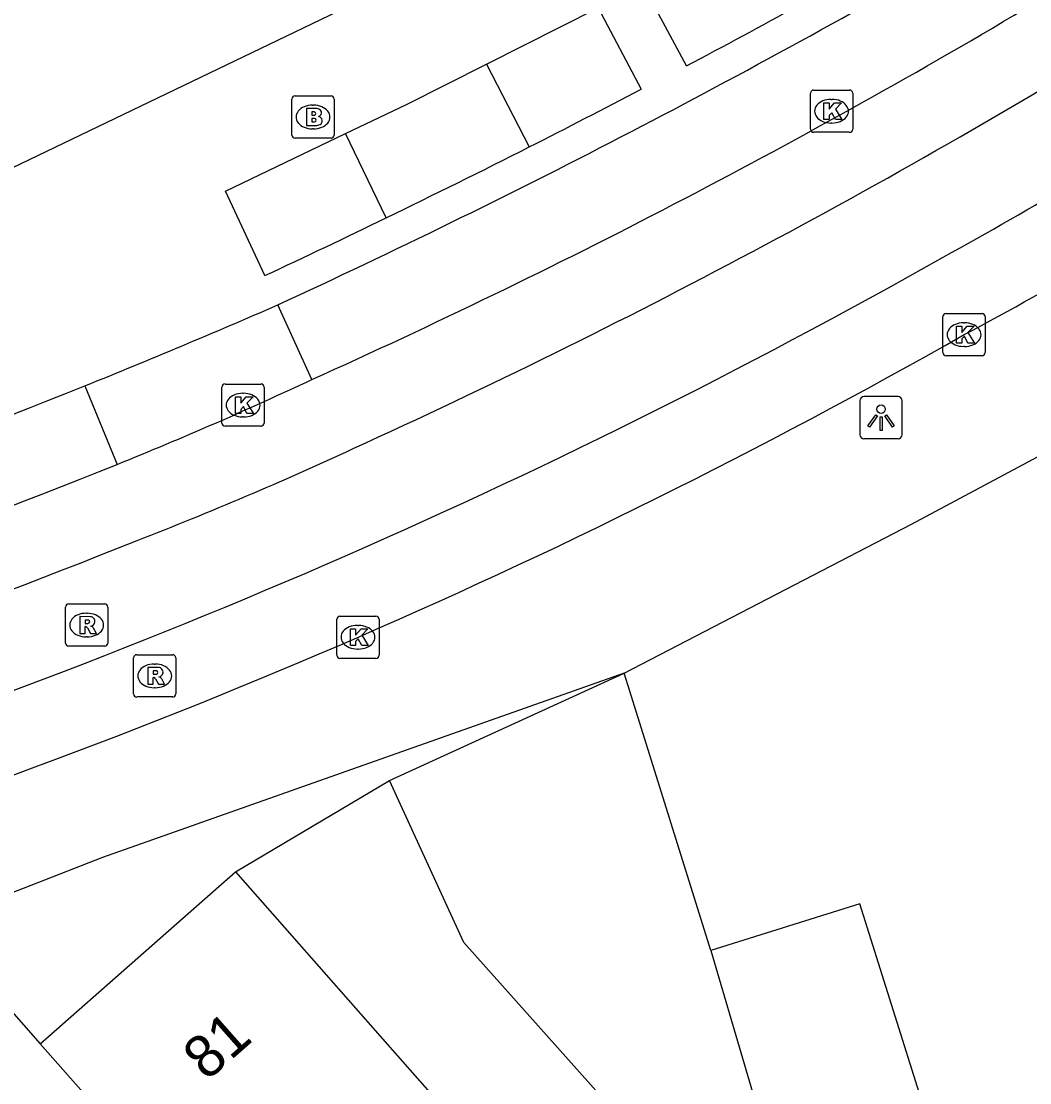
# Model space of a CAD drawing. Extents: x 161355 to 162026, y 386504 to 387459.
# Drawn here: x 161546.63 to 161570.51, y 386818.81 to 386843.94 of the extents above; entities that cross this region are included whole.
import ezdxf

# ---------------------------------------------------------------- set-up
doc = ezdxf.new("R2010")
doc.units = 0
for name, color, linetype in [('IMGEO_Brandkraan', 7, 'Continuous'), ('IMGEO_Groenvoorziening', 7, 'Continuous'), ('IMGEO_Kolk', 7, 'Continuous'), ('IMGEO_Lichtpunt', 7, 'Continuous'), ('IMGEO_Pand', 7, 'Continuous'), ('IMGEO_Pand_nummerreeks', 7, 'Continuous'), ('IMGEO_Rijbaan_lokaal_gesloten', 7, 'Continuous'), ('IMGEO_Rijbaan_lokaal_open', 7, 'Continuous'), ('IMGEO_Rioolput', 7, 'Continuous'), ('IMGEO_Voetpad_open', 7, 'Continuous')]:
    doc.layers.add(name, color=color, linetype=linetype)

msp = doc.modelspace()

# ---------------------------------------------------------------- linework, layer by layer
at = {"layer": 'IMGEO_Brandkraan'}
for p, q in [((161553.116, 386842.176), (161553.968, 386842.176)), ((161553.041, 386841.25), (161553.041, 386842.102)), ((161553.529, 386841.956), (161553.554, 386841.956)), ((161554.042, 386842.102), (161554.042, 386841.25)), ((161553.552, 386841.396), (161553.527, 386841.396)), ((161553.968, 386841.176), (161553.116, 386841.176))]:
    msp.add_line(p, q, dxfattribs=at)
for points in [[(161553.116, 386842.176), (161553.968, 386842.176)], [(161553.041, 386841.25), (161553.041, 386842.102)], [(161554.042, 386842.102), (161554.042, 386841.25)], [(161553.389, 386841.876), (161553.389, 386841.476), (161553.602, 386841.476)], [(161553.62, 386841.876), (161553.389, 386841.876)], [(161553.568, 386841.795), (161553.514, 386841.795), (161553.514, 386841.719)], [(161553.514, 386841.719), (161553.567, 386841.719)], [(161553.576, 386841.643), (161553.514, 386841.643), (161553.514, 386841.562)], [(161553.514, 386841.562), (161553.576, 386841.562)], [(161553.968, 386841.176), (161553.116, 386841.176)]]:
    msp.add_lwpolyline(points, dxfattribs=at)
for centre, radius, start, end in [((161553.118, 386842.1), 0.0765, 91.552, 178.448), ((161553.118, 386842.1), 0.0765, 91.552, 178.448), ((161553.966, 386842.1), 0.0765, 1.552, 88.448), ((161553.966, 386842.1), 0.0765, 1.552, 88.448), ((161553.569, 386841.757), 0.0379, 267.8285, 90.9355), ((161553.577, 386841.602), 0.0404, 269.8759, 90.5077), ((161553.624, 386841.731), 0.145, 59.4692, 91.5367), ((161553.649, 386841.778), 0.0922, 285.5137, 58.1501), ((161553.654, 386841.586), 0.105, 301.3115, 78.989), ((161553.608, 386841.727), 0.251, 268.6676, 293.5347), ((161553.118, 386841.252), 0.0765, 181.552, 268.448), ((161553.118, 386841.252), 0.0765, 181.552, 268.448), ((161553.966, 386841.252), 0.0765, 271.552, 358.448), ((161553.966, 386841.252), 0.0765, 271.552, 358.448)]:
    msp.add_arc(centre, radius, start, end, dxfattribs=at)
for centre, major_axis, ratio, start_param, end_param in [((161553.528, 386841.676), (-0.387, 0.002), 0.722429, 4.712389, 7.853982), ((161553.553, 386841.676), (-0.39, 0.002), 0.717154, 1.570796, 4.712389)]:
    msp.add_ellipse(centre, major_axis=major_axis, ratio=ratio, start_param=start_param, end_param=end_param, dxfattribs=at)
at = {"layer": 'IMGEO_Groenvoorziening'}
for points in [[(161557.648, 386842.93), (161558.662, 386840.969)], [(161555.27, 386839.287), (161554.307, 386841.282)]]:
    msp.add_lwpolyline(points, dxfattribs=at)
at = {"layer": 'IMGEO_Kolk'}
for p, q in [((161565.317, 386841.388), (161565.317, 386842.24)), ((161565.392, 386842.314), (161566.244, 386842.314)), ((161566.318, 386842.24), (161566.318, 386841.388)), ((161565.805, 386842.094), (161565.83, 386842.094)), ((161565.828, 386841.534), (161565.803, 386841.534)), ((161566.244, 386841.314), (161565.392, 386841.314)), ((161568.455, 386836.098), (161568.455, 386836.95)), ((161568.53, 386837.024), (161569.382, 386837.024)), ((161569.456, 386836.95), (161569.456, 386836.098)), ((161568.943, 386836.804), (161568.968, 386836.804)), ((161568.966, 386836.244), (161568.941, 386836.244)), ((161569.382, 386836.024), (161568.53, 386836.024)), ((161551.385, 386834.429), (161551.385, 386835.281)), ((161551.46, 386835.355), (161552.312, 386835.355)), ((161551.873, 386835.135), (161551.898, 386835.135)), ((161552.386, 386835.281), (161552.386, 386834.429)), ((161552.312, 386834.355), (161551.46, 386834.355)), ((161551.896, 386834.575), (161551.871, 386834.575)), ((161554.18, 386829.86), (161555.032, 386829.86)), ((161554.105, 386828.934), (161554.105, 386829.786)), ((161554.593, 386829.64), (161554.618, 386829.64)), ((161555.106, 386829.786), (161555.106, 386828.934)), ((161554.616, 386829.08), (161554.591, 386829.08)), ((161555.032, 386828.86), (161554.18, 386828.86))]:
    msp.add_line(p, q, dxfattribs=at)
for points in [[(161565.317, 386841.388), (161565.317, 386842.24)], [(161565.392, 386842.314), (161566.244, 386842.314)], [(161566.318, 386842.24), (161566.318, 386841.388)], [(161565.638, 386842.014), (161565.761, 386842.014), (161565.761, 386841.863), (161565.891, 386842.014), (161566.055, 386842.014), (161565.909, 386841.863), (161566.062, 386841.614), (161565.91, 386841.614), (161565.825, 386841.778), (161565.761, 386841.711), (161565.761, 386841.614), (161565.638, 386841.614), (161565.638, 386842.014)], [(161566.244, 386841.314), (161565.392, 386841.314)], [(161568.455, 386836.098), (161568.455, 386836.95)], [(161568.53, 386837.024), (161569.382, 386837.024)], [(161569.456, 386836.95), (161569.456, 386836.098)], [(161568.776, 386836.724), (161568.899, 386836.724), (161568.899, 386836.573), (161569.029, 386836.724), (161569.193, 386836.724), (161569.047, 386836.573), (161569.2, 386836.324), (161569.048, 386836.324), (161568.963, 386836.488), (161568.899, 386836.421), (161568.899, 386836.324), (161568.776, 386836.324), (161568.776, 386836.724)], [(161569.382, 386836.024), (161568.53, 386836.024)], [(161551.385, 386834.429), (161551.385, 386835.281)], [(161551.46, 386835.355), (161552.312, 386835.355)], [(161552.386, 386835.281), (161552.386, 386834.429)], [(161551.706, 386835.055), (161551.829, 386835.055), (161551.829, 386834.904), (161551.959, 386835.055), (161552.123, 386835.055), (161551.977, 386834.904), (161552.13, 386834.655), (161551.978, 386834.655), (161551.893, 386834.819), (161551.829, 386834.752), (161551.829, 386834.655), (161551.706, 386834.655), (161551.706, 386835.055)], [(161552.312, 386834.355), (161551.46, 386834.355)], [(161554.18, 386829.86), (161555.032, 386829.86)], [(161554.105, 386828.934), (161554.105, 386829.786)], [(161555.106, 386829.786), (161555.106, 386828.934)], [(161554.426, 386829.56), (161554.549, 386829.56), (161554.549, 386829.409), (161554.679, 386829.56), (161554.843, 386829.56), (161554.697, 386829.409), (161554.85, 386829.16), (161554.698, 386829.16), (161554.613, 386829.324), (161554.549, 386829.257), (161554.549, 386829.16), (161554.426, 386829.16), (161554.426, 386829.56)], [(161555.032, 386828.86), (161554.18, 386828.86)]]:
    msp.add_lwpolyline(points, dxfattribs=at)
for centre, start, end in [((161565.394, 386842.238), 91.552, 178.448), ((161565.394, 386842.238), 91.552, 178.448), ((161566.242, 386842.238), 1.552, 88.448), ((161566.242, 386842.238), 1.552, 88.448), ((161565.394, 386841.39), 181.552, 268.448), ((161565.394, 386841.39), 181.552, 268.448), ((161566.242, 386841.39), 271.552, 358.448), ((161566.242, 386841.39), 271.552, 358.448), ((161568.532, 386836.948), 91.552, 178.448), ((161568.532, 386836.948), 91.552, 178.448), ((161569.38, 386836.948), 1.552, 88.448), ((161569.38, 386836.948), 1.552, 88.448), ((161568.532, 386836.1), 181.552, 268.448), ((161568.532, 386836.1), 181.552, 268.448), ((161569.38, 386836.1), 271.552, 358.448), ((161569.38, 386836.1), 271.552, 358.448), ((161551.462, 386835.279), 91.552, 178.448), ((161551.462, 386835.279), 91.552, 178.448), ((161552.31, 386835.279), 1.552, 88.448), ((161552.31, 386835.279), 1.552, 88.448), ((161551.462, 386834.431), 181.552, 268.448), ((161551.462, 386834.431), 181.552, 268.448), ((161552.31, 386834.431), 271.552, 358.448), ((161552.31, 386834.431), 271.552, 358.448), ((161554.182, 386829.784), 91.552, 178.448), ((161554.182, 386829.784), 91.552, 178.448), ((161555.03, 386829.784), 1.552, 88.448), ((161555.03, 386829.784), 1.552, 88.448), ((161554.182, 386828.936), 181.552, 268.448), ((161554.182, 386828.936), 181.552, 268.448), ((161555.03, 386828.936), 271.552, 358.448), ((161555.03, 386828.936), 271.552, 358.448)]:
    msp.add_arc(centre, 0.0765, start, end, dxfattribs=at)
for centre, major_axis, ratio, start_param, end_param in [((161565.804, 386841.814), (-0.387, 0.002), 0.722429, 4.712389, 7.853982), ((161565.829, 386841.814), (-0.39, 0.002), 0.717154, 1.570796, 4.712389), ((161568.942, 386836.524), (-0.387, 0.002), 0.722429, 4.712389, 7.853982), ((161568.967, 386836.524), (-0.39, 0.002), 0.717154, 1.570796, 4.712389), ((161551.872, 386834.855), (-0.387, 0.002), 0.722429, 4.712389, 7.853982), ((161551.897, 386834.855), (-0.39, 0.002), 0.717154, 1.570796, 4.712389), ((161554.592, 386829.36), (-0.387, 0.002), 0.722429, 4.712389, 7.853982), ((161554.617, 386829.36), (-0.39, 0.002), 0.717154, 1.570796, 4.712389)]:
    msp.add_ellipse(centre, major_axis=major_axis, ratio=ratio, start_param=start_param, end_param=end_param, dxfattribs=at)
at = {"layer": 'IMGEO_Lichtpunt'}
for p, q in [((161566.491, 386834.962), (161566.491, 386834.155)), ((161566.491, 386834.962), (161566.491, 386834.155)), ((161567.393, 386835.057), (161566.585, 386835.057)), ((161567.393, 386835.057), (161566.585, 386835.057)), ((161567.487, 386834.155), (161567.487, 386834.962)), ((161567.487, 386834.155), (161567.487, 386834.962)), ((161566.585, 386834.061), (161567.393, 386834.061)), ((161566.585, 386834.061), (161567.393, 386834.061))]:
    msp.add_line(p, q, dxfattribs=at)
for points in [[(161566.865, 386834.626), (161566.904, 386834.598), (161566.716, 386834.336), (161566.678, 386834.363), (161566.865, 386834.626)], [(161567.077, 386834.598), (161567.115, 386834.625), (161567.302, 386834.363), (161567.263, 386834.335), (161567.077, 386834.598)], [(161566.967, 386834.578), (161567.014, 386834.578), (161567.014, 386834.256), (161566.967, 386834.256), (161566.967, 386834.578)]]:
    msp.add_lwpolyline(points, dxfattribs=at)
msp.add_circle((161566.99, 386834.76), 0.0994, dxfattribs=at)
for centre, start, end in [((161566.585, 386834.962), 90, 180), ((161566.585, 386834.962), 90, 180), ((161567.393, 386834.962), 0, 90), ((161567.393, 386834.962), 0, 90), ((161566.585, 386834.155), 180, 270), ((161566.585, 386834.155), 180, 270), ((161567.393, 386834.155), 270, 0), ((161567.393, 386834.155), 270, 360)]:
    msp.add_arc(centre, 0.0946, start, end, dxfattribs=at)
at = {"layer": 'IMGEO_Pand'}
for points in [[(161555.353, 386825.969), (161560.908, 386828.506)], [(161562.963, 386821.942), (161561.042, 386828.079), (161560.908, 386828.506)], [(161564.024, 386818.32), (161562.065, 386816.575), (161557.114, 386822.131), (161555.353, 386825.969)], [(161547.085, 386819.73), (161551.704, 386823.803)], [(161551.704, 386823.803), (161555.01, 386820.052), (161557.658, 386817.049), (161559.775, 386814.648), (161555.164, 386810.583)], [(161568.624, 386812.203), (161567.681, 386815.202), (161568.843, 386815.568), (161567.989, 386818.282), (161566.488, 386823.051), (161562.963, 386821.942)], [(161562.963, 386821.942), (161564.024, 386818.32)], [(161540.906, 386817.019), (161545.726, 386821.269), (161547.085, 386819.73)], [(161555.164, 386810.583), (161547.085, 386819.73)]]:
    msp.add_lwpolyline(points, dxfattribs=at)
at = {"layer": 'IMGEO_Rijbaan_lokaal_gesloten'}
for centre, radius, start, end in [((161484.617, 386988.619), 167.941, 294.21901, 300.71532), ((161483.765, 386989.11), 170.634, 294.48882, 301.57465), ((161507.605, 386948.155), 125.538, 298.78933, 302.11626), ((161526.3, 386916.738), 90.851, 298.00279, 302.67491), ((161491.859, 386973.935), 155.72, 287.22198, 299.29875), ((161494.805, 386967.101), 150.162, 286.97418, 299.59125), ((161514.694, 386918.245), 91.434, 291.97075, 295.12092), ((161518.235, 386912.068), 86.236, 291.1677, 294.86432), ((161488.255, 386984.249), 162.536, 281.2692, 291.90897), ((161488.231, 386983.377), 163.583, 281.3297, 291.94879)]:
    msp.add_arc(centre, radius, start, end, dxfattribs=at)
at = {"layer": 'IMGEO_Rijbaan_lokaal_open'}
for points in [[(161553.511, 386835.459), (161552.706, 386837.228)], [(161548.14, 386835.312), (161548.903, 386833.451)]]:
    msp.add_lwpolyline(points, dxfattribs=at)
msp.add_arc((161480.876, 387002.007), 179.755, 291.97487, 293.55325, dxfattribs=at)
at = {"layer": 'IMGEO_Rioolput'}
for p, q in [((161547.758, 386830.148), (161548.61, 386830.148)), ((161547.683, 386829.222), (161547.683, 386830.074)), ((161548.171, 386829.928), (161548.196, 386829.928)), ((161548.684, 386830.074), (161548.684, 386829.222)), ((161548.194, 386829.368), (161548.169, 386829.368)), ((161548.61, 386829.148), (161547.758, 386829.148)), ((161549.294, 386828.019), (161549.294, 386828.871)), ((161549.369, 386828.945), (161550.221, 386828.945)), ((161550.295, 386828.871), (161550.295, 386828.019)), ((161549.782, 386828.725), (161549.807, 386828.725)), ((161549.805, 386828.165), (161549.78, 386828.165)), ((161550.221, 386827.945), (161549.369, 386827.945))]:
    msp.add_line(p, q, dxfattribs=at)
for points in [[(161547.758, 386830.148), (161548.61, 386830.148)], [(161547.683, 386829.222), (161547.683, 386830.074)], [(161548.272, 386829.846), (161548.02, 386829.848), (161548.02, 386829.448)], [(161548.684, 386830.074), (161548.684, 386829.222)], [(161548.02, 386829.448), (161548.144, 386829.448), (161548.144, 386829.61), (161548.155, 386829.61)], [(161548.198, 386829.767), (161548.144, 386829.767), (161548.144, 386829.686)], [(161548.144, 386829.686), (161548.196, 386829.686)], [(161548.202, 386829.581), (161548.273, 386829.448), (161548.413, 386829.448), (161548.348, 386829.574)], [(161548.61, 386829.148), (161547.758, 386829.148)], [(161549.294, 386828.019), (161549.294, 386828.871)], [(161549.369, 386828.945), (161550.221, 386828.945)], [(161550.295, 386828.871), (161550.295, 386828.019)], [(161549.883, 386828.643), (161549.631, 386828.645), (161549.631, 386828.245)], [(161549.631, 386828.245), (161549.755, 386828.245), (161549.755, 386828.407), (161549.766, 386828.407)], [(161549.809, 386828.564), (161549.755, 386828.564), (161549.755, 386828.483)], [(161549.755, 386828.483), (161549.807, 386828.483)], [(161549.813, 386828.378), (161549.884, 386828.245), (161550.024, 386828.245), (161549.959, 386828.371)], [(161550.221, 386827.945), (161549.369, 386827.945)]]:
    msp.add_lwpolyline(points, dxfattribs=at)
for centre, radius, start, end in [((161547.76, 386830.072), 0.0765, 91.552, 178.448), ((161547.76, 386830.072), 0.0765, 91.552, 178.448), ((161548.608, 386830.072), 0.0765, 1.552, 88.448), ((161548.608, 386830.072), 0.0765, 1.552, 88.448), ((161548.271, 386829.736), 0.109, 350.3612, 89.416), ((161548.154, 386829.557), 0.0533, 26.0293, 88.6989), ((161548.18, 386829.875), 0.19, 274.7715, 282.9687), ((161548.204, 386829.671), 0.0964, 77.0061, 93.1865), ((161548.218, 386829.728), 0.0378, 276.6634, 79.6772), ((161548.269, 386829.736), 0.112, 277.5842, 350.9817), ((161548.253, 386829.521), 0.108, 29.5134, 73.7905), ((161547.76, 386829.224), 0.0765, 181.552, 268.448), ((161547.76, 386829.224), 0.0765, 181.552, 268.448), ((161548.608, 386829.224), 0.0765, 271.552, 358.448), ((161548.608, 386829.224), 0.0765, 271.552, 358.448), ((161549.371, 386828.869), 0.0765, 91.552, 178.448), ((161549.371, 386828.869), 0.0765, 91.552, 178.448), ((161550.219, 386828.869), 0.0765, 1.552, 88.448), ((161550.219, 386828.869), 0.0765, 1.552, 88.448), ((161549.882, 386828.533), 0.109, 350.3612, 89.416), ((161549.765, 386828.354), 0.0533, 26.0293, 88.6989), ((161549.791, 386828.672), 0.19, 274.7715, 282.9687), ((161549.815, 386828.468), 0.0964, 77.0061, 93.1865), ((161549.829, 386828.525), 0.0378, 276.6634, 79.6772), ((161549.88, 386828.533), 0.112, 277.5842, 350.9817), ((161549.864, 386828.318), 0.108, 29.5134, 73.7905), ((161549.371, 386828.021), 0.0765, 181.552, 268.448), ((161549.371, 386828.021), 0.0765, 181.552, 268.448), ((161550.219, 386828.021), 0.0765, 271.552, 358.448), ((161550.219, 386828.021), 0.0765, 271.552, 358.448)]:
    msp.add_arc(centre, radius, start, end, dxfattribs=at)
for centre, major_axis, ratio, start_param, end_param in [((161548.17, 386829.648), (-0.387, 0.002), 0.722429, 4.712389, 7.853982), ((161548.195, 386829.648), (-0.39, 0.002), 0.717154, 1.570796, 4.712389), ((161549.781, 386828.445), (-0.387, 0.002), 0.722429, 4.712389, 7.853982), ((161549.806, 386828.445), (-0.39, 0.002), 0.717154, 1.570796, 4.712389)]:
    msp.add_ellipse(centre, major_axis=major_axis, ratio=ratio, start_param=start_param, end_param=end_param, dxfattribs=at)
at = {"layer": 'IMGEO_Voetpad_open'}
for points in [[(161621.155, 386910.96), (161617.812, 386904.79), (161613.199, 386897.541), (161609.426, 386892.17), (161605.511, 386887.3), (161602.205, 386883.499), (161603.425, 386882.36), (161601.088, 386879.5), (161596.783, 386874.819), (161589.161, 386867.257), (161578.702, 386858.612), (161569.609, 386852.318), (161562.581, 386848.097), (161561.221, 386847.589), (161545.191, 386839.884)], [(161562.382, 386842.887), (161561.337, 386844.849)], [(161557.648, 386842.93), (161560.293, 386844.263), (161561.308, 386842.333)], [(161554.307, 386841.282), (161555.752, 386841.974), (161557.648, 386842.93)], [(161552.402, 386837.922), (161551.467, 386839.921), (161554.307, 386841.282)], [(161560.908, 386828.506), (161567.714, 386832.035), (161575.538, 386836.218)], [(161560.908, 386828.506), (161548.555, 386824.146), (161541.76, 386821.49), (161537.374, 386820.193), (161536.643, 386819.971)], [(161551.704, 386823.803), (161555.353, 386825.969)]]:
    msp.add_lwpolyline(points, dxfattribs=at)
for centre, radius, start, end in [((161470.098, 387016.33), 197.235, 294.76071, 300.01589), ((161503.019, 386956.03), 127.77, 297.68459, 299.04016), ((161472.76, 387010.858), 190.372, 296.82291, 297.71886), ((161466.736, 387022.091), 203.114, 295.84154, 296.90957), ((161467.201, 387020.633), 201.6, 295.00035, 295.90307), ((161489.01, 386981.291), 157.5, 281.08766, 292.05075)]:
    msp.add_arc(centre, radius, start, end, dxfattribs=at)

# ---------------------------------------------------------------- texts
at = {"layer": 'IMGEO_Pand_nummerreeks'}
msp.add_text('81', height=1, rotation=41.4064, dxfattribs=at).set_placement((161551.029, 386818.834))

doc.saveas('drawing.dxf')
